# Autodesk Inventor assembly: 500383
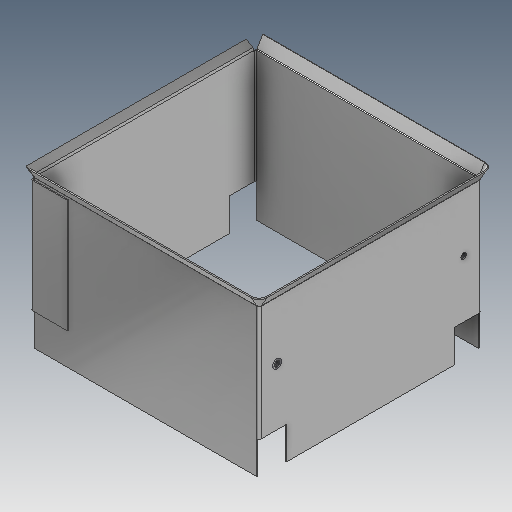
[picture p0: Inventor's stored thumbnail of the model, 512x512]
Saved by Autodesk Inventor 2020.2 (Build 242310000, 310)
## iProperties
Created: 1999-12
Part Number: 500383
Document SubType Name: Assembly
Designer: glanglot
Mass: 4038.98 g
Surface Area: 6461.55 cm^2
Volume: 611.024 cm^3
Density: 6.61019 g/cm^3
Control State: 0
Checked Out: False
Master: False
Shininess: 0.0
Length Units: 11269
Angle Units: 11279
Time Units: 11290
Mass Units: 11283
Length Display Precision: 3
Angle Display Precision: 2
Compacted: True
Dimensions: 332,2x218,6x323,8 mm
Mass: 4,039 kg
DocNumber: 500383.iam
Folder: 01 - Themengebiete\Simplification\01 - Packaging machine\
VDS_Category: 3D Komponenten
Density: 0.0
Volumn: 0.0
Area: 0.0
PropertySet Name: Model Information
Author: glanglot
Revision Number: -
Title: box
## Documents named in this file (5)
- D:\07 - DEMODATEN\OTX 2019 - Dataset - UPDATE - Dez2019\Designs\07-Packing machine\500383.iam
- D:\07 - DEMODATEN\OTX 2019 - Dataset - UPDATE - Dez2019\Designs\07-Packing machine\Parts\ADSK-011372.ipt
- D:\07 - DEMODATEN\OTX 2019 - Dataset - UPDATE - Dez2019\Designs\07-Packing machine\Parts\ADSK-011370.ipt
- D:\07 - DEMODATEN\OTX 2019 - Dataset - UPDATE - Dez2019\Designs\07-Packing machine\Parts\ADSK-011371.ipt
- D:\07 - DEMODATEN\OTX 2019 - Dataset - UPDATE - Dez2019\Designs\07-Packing machine\Parts\ADSK-011373.ipt
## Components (5 placed, 4 different names)
1. ADSK-011370:1 — Passend:1, Fluchtend:1, Passend:2, Flush:2, Flush:3, Mate:3, Einfügen:1, Insert:2, Mate:4, Fluchtend:4, Fluchtend:5
2. ADSK-011371:1 — Passend:1, Fluchtend:1, Passend:2
3. ADSK-011372:1 — Einfügen:1
4. ADSK-011372:2 — Insert:2
5. ADSK-011373:1 — Mate:4, Fluchtend:4, Fluchtend:5
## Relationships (11: Flush 5, Mate 4, Insert 2)
- Passend:1 [Mate]: ADSK-011370:1 ↔ ADSK-011371:1
- Fluchtend:1 [Flush]: ADSK-011370:1 ↔ ADSK-011371:1
- Passend:2 [Mate]: ADSK-011370:1 ↔ ADSK-011371:1
- Flush:2: ADSK-011370:1
- Flush:3: ADSK-011370:1
- Mate:3: ADSK-011370:1
- Einfügen:1 [Insert]: ADSK-011370:1 ↔ ADSK-011372:1
- Insert:2: ADSK-011370:1 ↔ ADSK-011372:2
- Mate:4: ADSK-011370:1 ↔ ADSK-011373:1
- Fluchtend:4 [Flush]: ADSK-011370:1 ↔ ADSK-011373:1
- Fluchtend:5 [Flush]: ADSK-011370:1 ↔ ADSK-011373:1
